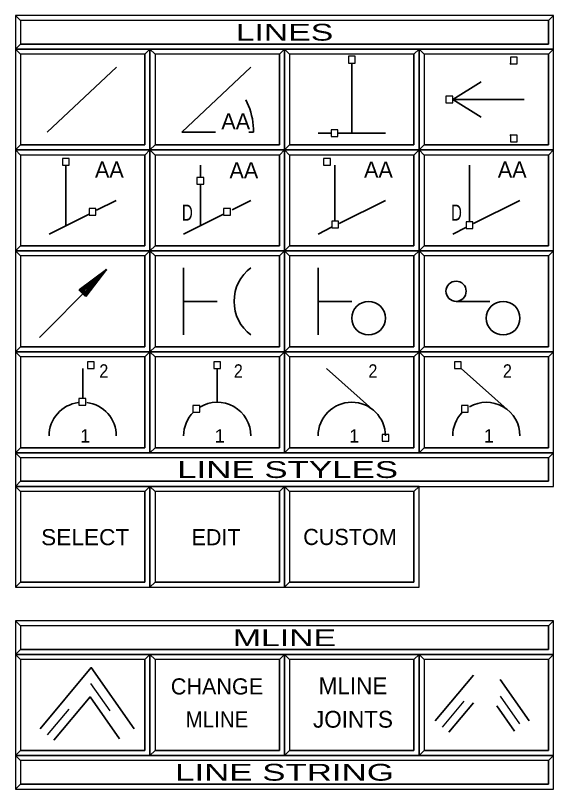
# Model space of a CAD drawing. Extents: x 95906.9 to 95918.9, y 90964.8 to 90972.9.
# Drawn here: x 95908.935 to 95910.535, y 90967.296 to 90969.589 of the extents above; entities that cross this region are included whole.
import ezdxf
from ezdxf.enums import TextEntityAlignment as Align

# ---------------------------------------------------------------- set-up
doc = ezdxf.new("R2010")
doc.units = 0
doc.header["$LTSCALE"] = 0.019
doc.linetypes.add('DOT_DASHED', pattern=[7.7, 5, -1.2, 0.3, -1.2])
doc.linetypes.add('MEDIUM_DASHED', pattern=[4.5, 3, -1.5])
for name, color, linetype, lineweight in [('1', 7, 'Continuous', 25), ('11', 7, 'Continuous', 25), ('12', 7, 'Continuous', 25), ('17', 7, 'Continuous', 25), ('2', 7, 'Continuous', 13), ('21', 7, 'Continuous', 25), ('3', 7, 'Continuous', 25), ('4', 7, 'Continuous', 35), ('6', 7, 'Continuous', 35), ('7', 7, 'Continuous', 35)]:
    doc.layers.add(name, color=color, linetype=linetype, lineweight=lineweight)

msp = doc.modelspace()

# ---------------------------------------------------------------- linework, layer by layer
at = {"layer": '1'}
for points in [[(95908.9346, 90969.4887), (95910.5346, 90969.4887), (95910.5346, 90969.5887), (95908.9346, 90969.5887)], [(95908.9346, 90969.1887), (95909.3346, 90969.1887), (95909.3346, 90969.4887), (95908.9346, 90969.4887)], [(95909.3346, 90969.1887), (95909.7346, 90969.1887), (95909.7346, 90969.4887), (95909.3346, 90969.4887)], [(95909.7346, 90969.1887), (95910.1346, 90969.1887), (95910.1346, 90969.4887), (95909.7346, 90969.4887)], [(95910.1346, 90969.1887), (95910.5346, 90969.1887), (95910.5346, 90969.4887), (95910.1346, 90969.4887)], [(95908.9346, 90968.8887), (95909.3346, 90968.8887), (95909.3346, 90969.1887), (95908.9346, 90969.1887)], [(95909.3346, 90968.8887), (95909.7346, 90968.8887), (95909.7346, 90969.1887), (95909.3346, 90969.1887)], [(95909.7346, 90968.8887), (95910.1346, 90968.8887), (95910.1346, 90969.1887), (95909.7346, 90969.1887)], [(95910.1346, 90968.8887), (95910.5346, 90968.8887), (95910.5346, 90969.1887), (95910.1346, 90969.1887)], [(95908.9346, 90968.5887), (95909.3346, 90968.5887), (95909.3346, 90968.8887), (95908.9346, 90968.8887)], [(95909.3346, 90968.5887), (95909.7346, 90968.5887), (95909.7346, 90968.8887), (95909.3346, 90968.8887)], [(95909.7346, 90968.5887), (95910.1346, 90968.5887), (95910.1346, 90968.8887), (95909.7346, 90968.8887)], [(95910.1346, 90968.5887), (95910.5346, 90968.5887), (95910.5346, 90968.8887), (95910.1346, 90968.8887)], [(95908.9346, 90968.2887), (95909.3346, 90968.2887), (95909.3346, 90968.5887), (95908.9346, 90968.5887)], [(95909.3346, 90968.2887), (95909.7346, 90968.2887), (95909.7346, 90968.5887), (95909.3346, 90968.5887)], [(95909.7346, 90968.2887), (95910.1346, 90968.2887), (95910.1346, 90968.5887), (95909.7346, 90968.5887)], [(95910.1346, 90968.2887), (95910.5346, 90968.2887), (95910.5346, 90968.5887), (95910.1346, 90968.5887)], [(95908.9346, 90968.1887), (95910.5346, 90968.1887), (95910.5346, 90968.2887), (95908.9346, 90968.2887)], [(95908.9346, 90967.8887), (95909.3346, 90967.8887), (95909.3346, 90968.1887), (95908.9346, 90968.1887)], [(95909.3346, 90967.8887), (95909.7346, 90967.8887), (95909.7346, 90968.1887), (95909.3346, 90968.1887)], [(95909.7346, 90967.8887), (95910.1346, 90967.8887), (95910.1346, 90968.1887), (95909.7346, 90968.1887)], [(95908.9346, 90967.6887), (95910.5346, 90967.6887), (95910.5346, 90967.7887), (95908.9346, 90967.7887)], [(95908.9346, 90967.3887), (95909.3346, 90967.3887), (95909.3346, 90967.6887), (95908.9346, 90967.6887)], [(95909.3346, 90967.3887), (95909.7346, 90967.3887), (95909.7346, 90967.6887), (95909.3346, 90967.6887)], [(95909.7346, 90967.3887), (95910.1346, 90967.3887), (95910.1346, 90967.6887), (95909.7346, 90967.6887)], [(95910.1346, 90967.3887), (95910.5346, 90967.3887), (95910.5346, 90967.6887), (95910.1346, 90967.6887)], [(95908.9346, 90967.2887), (95910.5346, 90967.2887), (95910.5346, 90967.3887), (95908.9346, 90967.3887)]]:
    msp.add_lwpolyline(points, close=True, dxfattribs=at)
at = {"layer": '11'}
for points in [[(95908.9496, 90969.2037), (95909.3196, 90969.2037), (95909.3196, 90969.4737), (95908.9496, 90969.4737)], [(95909.3496, 90969.2037), (95909.7196, 90969.2037), (95909.7196, 90969.4737), (95909.3496, 90969.4737)], [(95909.7496, 90969.2037), (95910.1196, 90969.2037), (95910.1196, 90969.4737), (95909.7496, 90969.4737)], [(95910.1496, 90969.2037), (95910.5196, 90969.2037), (95910.5196, 90969.4737), (95910.1496, 90969.4737)], [(95908.9496, 90968.9037), (95909.3196, 90968.9037), (95909.3196, 90969.1737), (95908.9496, 90969.1737)], [(95909.3496, 90968.9037), (95909.7196, 90968.9037), (95909.7196, 90969.1737), (95909.3496, 90969.1737)], [(95909.7496, 90968.9037), (95910.1196, 90968.9037), (95910.1196, 90969.1737), (95909.7496, 90969.1737)], [(95910.1496, 90968.9037), (95910.5196, 90968.9037), (95910.5196, 90969.1737), (95910.1496, 90969.1737)], [(95908.9496, 90968.6037), (95909.3196, 90968.6037), (95909.3196, 90968.8737), (95908.9496, 90968.8737)], [(95909.3496, 90968.6037), (95909.7196, 90968.6037), (95909.7196, 90968.8737), (95909.3496, 90968.8737)], [(95909.7496, 90968.6037), (95910.1196, 90968.6037), (95910.1196, 90968.8737), (95909.7496, 90968.8737)], [(95910.1496, 90968.6037), (95910.5196, 90968.6037), (95910.5196, 90968.8737), (95910.1496, 90968.8737)], [(95908.9496, 90968.3037), (95909.3196, 90968.3037), (95909.3196, 90968.5737), (95908.9496, 90968.5737)], [(95909.3496, 90968.3037), (95909.7196, 90968.3037), (95909.7196, 90968.5737), (95909.3496, 90968.5737)], [(95909.7496, 90968.3037), (95910.1196, 90968.3037), (95910.1196, 90968.5737), (95909.7496, 90968.5737)], [(95910.1496, 90968.3037), (95910.5196, 90968.3037), (95910.5196, 90968.5737), (95910.1496, 90968.5737)], [(95908.9496, 90967.9037), (95909.3196, 90967.9037), (95909.3196, 90968.1737), (95908.9496, 90968.1737)], [(95909.3496, 90967.9037), (95909.7196, 90967.9037), (95909.7196, 90968.1737), (95909.3496, 90968.1737)], [(95909.7496, 90967.9037), (95910.1196, 90967.9037), (95910.1196, 90968.1737), (95909.7496, 90968.1737)], [(95908.9496, 90967.4037), (95909.3196, 90967.4037), (95909.3196, 90967.6737), (95908.9496, 90967.6737)], [(95909.3496, 90967.4037), (95909.7196, 90967.4037), (95909.7196, 90967.6737), (95909.3496, 90967.6737)], [(95909.7496, 90967.4037), (95910.1196, 90967.4037), (95910.1196, 90967.6737), (95909.7496, 90967.6737)], [(95910.1496, 90967.4037), (95910.5196, 90967.4037), (95910.5196, 90967.6737), (95910.1496, 90967.6737)]]:
    msp.add_lwpolyline(points, close=True, dxfattribs=at)
at = {"layer": '12'}
msp.add_lwpolyline([(95908.9496, 90969.2037), (95909.3196, 90969.2037), (95909.3196, 90969.4737), (95908.9496, 90969.4737)], close=True, dxfattribs=at)
at = {"layer": '17'}
for points in [[(95908.9496, 90969.5037), (95910.5196, 90969.5037), (95910.5196, 90969.5737), (95908.9496, 90969.5737)], [(95908.9496, 90967.7037), (95910.5196, 90967.7037), (95910.5196, 90967.7737), (95908.9496, 90967.7737)], [(95908.9496, 90967.3037), (95910.5196, 90967.3037), (95910.5196, 90967.3737), (95908.9496, 90967.3737)]]:
    msp.add_lwpolyline(points, close=True, dxfattribs=at)
at = {"layer": '2'}
for points in [[(95908.9346, 90969.5887), (95908.9346, 90969.4887), (95908.9496, 90969.5037), (95908.9496, 90969.5737), (95910.5196, 90969.5737), (95910.5346, 90969.5887)], [(95908.9346, 90969.4887), (95908.9346, 90969.1887), (95908.9496, 90969.2037), (95908.9496, 90969.4737), (95909.3196, 90969.4737), (95909.3346, 90969.4887)], [(95909.3346, 90969.4887), (95909.3346, 90969.1887), (95909.3496, 90969.2037), (95909.3496, 90969.4737), (95909.7196, 90969.4737), (95909.7346, 90969.4887)], [(95909.7346, 90969.4887), (95909.7346, 90969.1887), (95909.7496, 90969.2037), (95909.7496, 90969.4737), (95910.1196, 90969.4737), (95910.1346, 90969.4887)], [(95910.1346, 90969.4887), (95910.1346, 90969.1887), (95910.1496, 90969.2037), (95910.1496, 90969.4737), (95910.5196, 90969.4737), (95910.5346, 90969.4887)], [(95908.9346, 90969.1887), (95908.9346, 90968.8887), (95908.9496, 90968.9037), (95908.9496, 90969.1737), (95909.3196, 90969.1737), (95909.3346, 90969.1887)], [(95909.3346, 90969.1887), (95909.3346, 90968.8887), (95909.3496, 90968.9037), (95909.3496, 90969.1737), (95909.7196, 90969.1737), (95909.7346, 90969.1887)], [(95909.7346, 90969.1887), (95909.7346, 90968.8887), (95909.7496, 90968.9037), (95909.7496, 90969.1737), (95910.1196, 90969.1737), (95910.1346, 90969.1887)], [(95910.1346, 90969.1887), (95910.1346, 90968.8887), (95910.1496, 90968.9037), (95910.1496, 90969.1737), (95910.5196, 90969.1737), (95910.5346, 90969.1887)], [(95908.9346, 90968.8887), (95908.9346, 90968.5887), (95908.9496, 90968.6037), (95908.9496, 90968.8737), (95909.3196, 90968.8737), (95909.3346, 90968.8887)], [(95909.3346, 90968.8887), (95909.3346, 90968.5887), (95909.3496, 90968.6037), (95909.3496, 90968.8737), (95909.7196, 90968.8737), (95909.7346, 90968.8887)], [(95909.7346, 90968.8887), (95909.7346, 90968.5887), (95909.7496, 90968.6037), (95909.7496, 90968.8737), (95910.1196, 90968.8737), (95910.1346, 90968.8887)], [(95910.1346, 90968.8887), (95910.1346, 90968.5887), (95910.1496, 90968.6037), (95910.1496, 90968.8737), (95910.5196, 90968.8737), (95910.5346, 90968.8887)], [(95908.9346, 90968.5887), (95908.9346, 90968.2887), (95908.9496, 90968.3037), (95908.9496, 90968.5737), (95909.3196, 90968.5737), (95909.3346, 90968.5887)], [(95909.3346, 90968.5887), (95909.3346, 90968.2887), (95909.3496, 90968.3037), (95909.3496, 90968.5737), (95909.7196, 90968.5737), (95909.7346, 90968.5887)], [(95909.7346, 90968.5887), (95909.7346, 90968.2887), (95909.7496, 90968.3037), (95909.7496, 90968.5737), (95910.1196, 90968.5737), (95910.1346, 90968.5887)], [(95910.1346, 90968.5887), (95910.1346, 90968.2887), (95910.1496, 90968.3037), (95910.1496, 90968.5737), (95910.5196, 90968.5737), (95910.5346, 90968.5887)], [(95908.9346, 90968.2887), (95908.9346, 90968.1887), (95908.9496, 90968.2037), (95908.9496, 90968.2737), (95910.5196, 90968.2737), (95910.5346, 90968.2887)], [(95908.9346, 90968.1887), (95908.9346, 90967.8887), (95908.9496, 90967.9037), (95908.9496, 90968.1737), (95909.3196, 90968.1737), (95909.3346, 90968.1887)], [(95909.3346, 90968.1887), (95909.3346, 90967.8887), (95909.3496, 90967.9037), (95909.3496, 90968.1737), (95909.7196, 90968.1737), (95909.7346, 90968.1887)], [(95909.7346, 90968.1887), (95909.7346, 90967.8887), (95909.7496, 90967.9037), (95909.7496, 90968.1737), (95910.1196, 90968.1737), (95910.1346, 90968.1887)], [(95909.7346, 90968.1887), (95909.7346, 90967.8887), (95909.7496, 90967.9037), (95909.7496, 90968.1737), (95910.1196, 90968.1737), (95910.1346, 90968.1887)], [(95908.9346, 90967.7887), (95908.9346, 90967.6887), (95908.9496, 90967.7037), (95908.9496, 90967.7737), (95910.5196, 90967.7737), (95910.5346, 90967.7887)], [(95908.9346, 90967.6887), (95908.9346, 90967.3887), (95908.9496, 90967.4037), (95908.9496, 90967.6737), (95909.3196, 90967.6737), (95909.3346, 90967.6887)], [(95909.3346, 90967.6887), (95909.3346, 90967.3887), (95909.3496, 90967.4037), (95909.3496, 90967.6737), (95909.7196, 90967.6737), (95909.7346, 90967.6887)], [(95909.7346, 90967.6887), (95909.7346, 90967.3887), (95909.7496, 90967.4037), (95909.7496, 90967.6737), (95910.1196, 90967.6737), (95910.1346, 90967.6887)], [(95910.1346, 90967.6887), (95910.1346, 90967.3887), (95910.1496, 90967.4037), (95910.1496, 90967.6737), (95910.5196, 90967.6737), (95910.5346, 90967.6887)], [(95908.9346, 90967.3887), (95908.9346, 90967.2887), (95908.9496, 90967.3037), (95908.9496, 90967.3737), (95910.5196, 90967.3737), (95910.5346, 90967.3887)]]:
    msp.add_lwpolyline(points, close=True, dxfattribs=at)
at = {"layer": '21'}
msp.add_lwpolyline([(95908.9496, 90968.2037), (95910.5196, 90968.2037), (95910.5196, 90968.2737), (95908.9496, 90968.2737)], close=True, dxfattribs=at)
at = {"layer": '3'}
for points in [[(95908.9346, 90969.4887), (95910.5346, 90969.4887), (95910.5346, 90969.5887), (95910.5196, 90969.5737), (95910.5196, 90969.5037), (95908.9496, 90969.5037)], [(95908.9346, 90969.1887), (95909.3346, 90969.1887), (95909.3346, 90969.4887), (95909.3196, 90969.4737), (95909.3196, 90969.2037), (95908.9496, 90969.2037)], [(95909.3346, 90969.1887), (95909.7346, 90969.1887), (95909.7346, 90969.4887), (95909.7196, 90969.4737), (95909.7196, 90969.2037), (95909.3496, 90969.2037)], [(95909.7346, 90969.1887), (95910.1346, 90969.1887), (95910.1346, 90969.4887), (95910.1196, 90969.4737), (95910.1196, 90969.2037), (95909.7496, 90969.2037)], [(95910.1346, 90969.1887), (95910.5346, 90969.1887), (95910.5346, 90969.4887), (95910.5196, 90969.4737), (95910.5196, 90969.2037), (95910.1496, 90969.2037)], [(95908.9346, 90968.8887), (95909.3346, 90968.8887), (95909.3346, 90969.1887), (95909.3196, 90969.1737), (95909.3196, 90968.9037), (95908.9496, 90968.9037)], [(95909.3346, 90968.8887), (95909.7346, 90968.8887), (95909.7346, 90969.1887), (95909.7196, 90969.1737), (95909.7196, 90968.9037), (95909.3496, 90968.9037)], [(95909.7346, 90968.8887), (95910.1346, 90968.8887), (95910.1346, 90969.1887), (95910.1196, 90969.1737), (95910.1196, 90968.9037), (95909.7496, 90968.9037)], [(95910.1346, 90968.8887), (95910.5346, 90968.8887), (95910.5346, 90969.1887), (95910.5196, 90969.1737), (95910.5196, 90968.9037), (95910.1496, 90968.9037)], [(95908.9346, 90968.5887), (95909.3346, 90968.5887), (95909.3346, 90968.8887), (95909.3196, 90968.8737), (95909.3196, 90968.6037), (95908.9496, 90968.6037)], [(95909.3346, 90968.5887), (95909.7346, 90968.5887), (95909.7346, 90968.8887), (95909.7196, 90968.8737), (95909.7196, 90968.6037), (95909.3496, 90968.6037)], [(95909.7346, 90968.5887), (95910.1346, 90968.5887), (95910.1346, 90968.8887), (95910.1196, 90968.8737), (95910.1196, 90968.6037), (95909.7496, 90968.6037)], [(95910.1346, 90968.5887), (95910.5346, 90968.5887), (95910.5346, 90968.8887), (95910.5196, 90968.8737), (95910.5196, 90968.6037), (95910.1496, 90968.6037)], [(95908.9346, 90968.2887), (95909.3346, 90968.2887), (95909.3346, 90968.5887), (95909.3196, 90968.5737), (95909.3196, 90968.3037), (95908.9496, 90968.3037)], [(95909.3346, 90968.2887), (95909.7346, 90968.2887), (95909.7346, 90968.5887), (95909.7196, 90968.5737), (95909.7196, 90968.3037), (95909.3496, 90968.3037)], [(95909.7346, 90968.2887), (95910.1346, 90968.2887), (95910.1346, 90968.5887), (95910.1196, 90968.5737), (95910.1196, 90968.3037), (95909.7496, 90968.3037)], [(95910.1346, 90968.2887), (95910.5346, 90968.2887), (95910.5346, 90968.5887), (95910.5196, 90968.5737), (95910.5196, 90968.3037), (95910.1496, 90968.3037)], [(95908.9346, 90968.1887), (95910.5346, 90968.1887), (95910.5346, 90968.2887), (95910.5196, 90968.2737), (95910.5196, 90968.2037), (95908.9496, 90968.2037)], [(95908.9346, 90967.8887), (95909.3346, 90967.8887), (95909.3346, 90968.1887), (95909.3196, 90968.1737), (95909.3196, 90967.9037), (95908.9496, 90967.9037)], [(95909.3346, 90967.8887), (95909.7346, 90967.8887), (95909.7346, 90968.1887), (95909.7196, 90968.1737), (95909.7196, 90967.9037), (95909.3496, 90967.9037)], [(95909.7346, 90967.8887), (95910.1346, 90967.8887), (95910.1346, 90968.1887), (95910.1196, 90968.1737), (95910.1196, 90967.9037), (95909.7496, 90967.9037)], [(95908.9346, 90967.6887), (95910.5346, 90967.6887), (95910.5346, 90967.7887), (95910.5196, 90967.7737), (95910.5196, 90967.7037), (95908.9496, 90967.7037)], [(95908.9346, 90967.3887), (95909.3346, 90967.3887), (95909.3346, 90967.6887), (95909.3196, 90967.6737), (95909.3196, 90967.4037), (95908.9496, 90967.4037)], [(95909.3346, 90967.3887), (95909.7346, 90967.3887), (95909.7346, 90967.6887), (95909.7196, 90967.6737), (95909.7196, 90967.4037), (95909.3496, 90967.4037)], [(95909.7346, 90967.3887), (95910.1346, 90967.3887), (95910.1346, 90967.6887), (95910.1196, 90967.6737), (95910.1196, 90967.4037), (95909.7496, 90967.4037)], [(95910.1346, 90967.3887), (95910.5346, 90967.3887), (95910.5346, 90967.6887), (95910.5196, 90967.6737), (95910.5196, 90967.4037), (95910.1496, 90967.4037)], [(95908.9346, 90967.2887), (95910.5346, 90967.2887), (95910.5346, 90967.3887), (95910.5196, 90967.3737), (95910.5196, 90967.3037), (95908.9496, 90967.3037)]]:
    msp.add_lwpolyline(points, close=True, dxfattribs=at)
at = {"layer": '4'}
for p, q in [((95908.9496, 90969.5737), (95908.9346, 90969.5887)), ((95908.9496, 90969.4737), (95908.9346, 90969.4887)), ((95909.3496, 90969.4737), (95909.3346, 90969.4887)), ((95909.7496, 90969.4737), (95909.7346, 90969.4887)), ((95910.1496, 90969.4737), (95910.1346, 90969.4887)), ((95908.9496, 90969.1737), (95908.9346, 90969.1887)), ((95909.3496, 90969.1737), (95909.3346, 90969.1887)), ((95909.7496, 90969.1737), (95909.7346, 90969.1887)), ((95910.1496, 90969.1737), (95910.1346, 90969.1887)), ((95908.9496, 90968.8737), (95908.9346, 90968.8887)), ((95909.3496, 90968.8737), (95909.3346, 90968.8887)), ((95909.7496, 90968.8737), (95909.7346, 90968.8887)), ((95910.1496, 90968.8737), (95910.1346, 90968.8887)), ((95908.9496, 90968.5737), (95908.9346, 90968.5887)), ((95909.3496, 90968.5737), (95909.3346, 90968.5887)), ((95909.7496, 90968.5737), (95909.7346, 90968.5887)), ((95910.1496, 90968.5737), (95910.1346, 90968.5887)), ((95908.9496, 90968.2737), (95908.9346, 90968.2887)), ((95908.9496, 90968.1737), (95908.9346, 90968.1887)), ((95909.3496, 90968.1737), (95909.3346, 90968.1887)), ((95909.7496, 90968.1737), (95909.7346, 90968.1887)), ((95908.9496, 90967.7737), (95908.9346, 90967.7887)), ((95908.9496, 90967.6737), (95908.9346, 90967.6887)), ((95909.3496, 90967.6737), (95909.3346, 90967.6887)), ((95909.7496, 90967.6737), (95909.7346, 90967.6887)), ((95910.1496, 90967.6737), (95910.1346, 90967.6887)), ((95908.9496, 90967.3737), (95908.9346, 90967.3887))]:
    msp.add_line(p, q, dxfattribs=at)
at = {"layer": '6'}
for p, q in [((95909.029, 90969.2412), (95909.235, 90969.435)), ((95909.429, 90969.2412), (95909.635, 90969.435)), ((95909.9346, 90969.2387), (95909.9346, 90969.4472)), ((95910.2346, 90969.3387), (95910.4467, 90969.3387)), ((95909.8346, 90969.2387), (95909.871, 90969.2387)), ((95910.0346, 90969.2387), (95909.8929, 90969.2387)), ((95909.0846, 90968.9637), (95909.0846, 90969.1437)), ((95909.4846, 90969.1437), (95909.4846, 90969.1098)), ((95909.8846, 90969.1437), (95909.8846, 90968.9781)), ((95910.2846, 90969.1437), (95910.2846, 90968.9755)), ((95909.4846, 90968.9637), (95909.4846, 90969.0853)), ((95909.2346, 90969.0387), (95909.176, 90969.0094)), ((95909.6346, 90969.0387), (95909.5795, 90969.0112)), ((95910.0346, 90969.0387), (95909.8969, 90968.9699)), ((95910.4346, 90969.0387), (95910.2969, 90968.9698)), ((95909.0346, 90968.9387), (95909.1534, 90968.9981)), ((95909.4346, 90968.9387), (95909.5532, 90968.998)), ((95909.8346, 90968.9387), (95909.8747, 90968.9588)), ((95910.2346, 90968.9387), (95910.2736, 90968.9582)), ((95909.4346, 90968.8387), (95909.4346, 90968.6387)), ((95909.8346, 90968.8387), (95909.8346, 90968.6387)), ((95909.1639, 90968.7895), (95909.0059, 90968.6315)), ((95909.1346, 90968.5387), (95909.1346, 90968.4525)), ((95909.5346, 90968.4387), (95909.5346, 90968.5387)), ((95910.0053, 90968.4094), (95909.8596, 90968.5387)), ((95910.4053, 90968.4094), (95910.2596, 90968.5387)), ((95910.1827, 90967.4916), (95910.2965, 90967.6273)), ((95910.376, 90967.6147), (95910.4622, 90967.4916)), ((95910.2233, 90967.4576), (95910.2965, 90967.5449)), ((95910.3661, 90967.5365), (95910.4188, 90967.4612))]:
    msp.add_line(p, q, dxfattribs=at)
at = {"layer": '6', "linetype": 'MEDIUM_DASHED'}
for p, q in [((95910.2346, 90969.3387), (95910.4063, 90969.4443)), ((95910.2346, 90969.3387), (95910.4063, 90969.2331)), ((95909.429, 90969.2412), (95909.6429, 90969.2412)), ((95909.4346, 90968.7387), (95909.5846, 90968.7387)), ((95909.8346, 90968.7387), (95909.9846, 90968.7387)), ((95910.2446, 90968.7387), (95910.3846, 90968.7387))]:
    msp.add_line(p, q, dxfattribs=at)
at = {"layer": '6', "lineweight": 40}
for p, q in [((95909.205, 90968.8333), (95909.1242, 90968.7727)), ((95909.205, 90968.8333), (95909.1441, 90968.7528)), ((95909.1905, 90968.8188), (95909.1285, 90968.7724)), ((95909.1905, 90968.8188), (95909.1438, 90968.7573)), ((95909.1758, 90968.8042), (95909.133, 90968.7721)), ((95909.1612, 90968.7897), (95909.1374, 90968.7718)), ((95909.1612, 90968.7897), (95909.1432, 90968.766)), ((95909.1758, 90968.8042), (95909.1435, 90968.7616)), ((95909.1441, 90968.7528), (95909.1242, 90968.7727)), ((95909.1438, 90968.7573), (95909.1285, 90968.7724)), ((95909.1435, 90968.7616), (95909.133, 90968.7721)), ((95909.1432, 90968.766), (95909.1374, 90968.7718))]:
    msp.add_line(p, q, dxfattribs=at)
at = {"layer": '6', "linetype": 'DOT_DASHED', "lineweight": 25}
for p, q in [((95910.2045, 90967.4733), (95910.2965, 90967.583)), ((95910.376, 90967.5651), (95910.4389, 90967.4753))]:
    msp.add_line(p, q, dxfattribs=at)
at = {"layer": '6', "lineweight": 25}
for points in [[(95909.9246, 90969.4472), (95909.9446, 90969.4472), (95909.9446, 90969.4672), (95909.9246, 90969.4672)], [(95910.4063, 90969.4443), (95910.4263, 90969.4443), (95910.4263, 90969.4643), (95910.4063, 90969.4643)], [(95910.2146, 90969.3287), (95910.2346, 90969.3287), (95910.2346, 90969.3487), (95910.2146, 90969.3487)], [(95909.8729, 90969.2289), (95909.8929, 90969.2289), (95909.8929, 90969.2489), (95909.8729, 90969.2489)], [(95910.4063, 90969.2131), (95910.4263, 90969.2131), (95910.4263, 90969.2331), (95910.4063, 90969.2331)], [(95909.0746, 90969.1437), (95909.0946, 90969.1437), (95909.0946, 90969.1637), (95909.0746, 90969.1637)], [(95909.8509, 90969.1437), (95909.8709, 90969.1437), (95909.8709, 90969.1637), (95909.8509, 90969.1637)], [(95909.4743, 90969.0872), (95909.4943, 90969.0872), (95909.4943, 90969.1072), (95909.4743, 90969.1072)], [(95909.1536, 90968.995), (95909.1736, 90968.995), (95909.1736, 90969.015), (95909.1536, 90969.015)], [(95909.5536, 90968.995), (95909.5736, 90968.995), (95909.5736, 90969.015), (95909.5536, 90969.015)], [(95909.8754, 90968.9574), (95909.8954, 90968.9574), (95909.8954, 90968.9774), (95909.8754, 90968.9774)], [(95910.275, 90968.9555), (95910.295, 90968.9555), (95910.295, 90968.9755), (95910.275, 90968.9755)], [(95909.1486, 90968.5387), (95909.1686, 90968.5387), (95909.1686, 90968.5587), (95909.1486, 90968.5587)], [(95909.5246, 90968.5387), (95909.5446, 90968.5387), (95909.5446, 90968.5587), (95909.5246, 90968.5587)], [(95910.2396, 90968.5387), (95910.2596, 90968.5387), (95910.2596, 90968.5587), (95910.2396, 90968.5587)], [(95909.1236, 90968.4299), (95909.1436, 90968.4299), (95909.1436, 90968.4499), (95909.1236, 90968.4499)], [(95909.4625, 90968.4092), (95909.4825, 90968.4092), (95909.4825, 90968.4292), (95909.4625, 90968.4292)], [(95910.2604, 90968.4092), (95910.2804, 90968.4092), (95910.2804, 90968.4292), (95910.2604, 90968.4292)], [(95910.0249, 90968.3226), (95910.0449, 90968.3226), (95910.0449, 90968.3426), (95910.0249, 90968.3426)]]:
    msp.add_lwpolyline(points, close=True, dxfattribs=at)
at = {"layer": '6'}
for points in [[(95909.0079, 90967.4681), (95909.1602, 90967.6497), (95909.2874, 90967.4681)], [(95909.0485, 90967.4341), (95909.1564, 90967.5628), (95909.244, 90967.4377)]]:
    msp.add_lwpolyline(points, dxfattribs=at)
at = {"layer": '6', "linetype": 'DOT_DASHED', "lineweight": 25}
msp.add_lwpolyline([(95909.0297, 90967.4498), (95909.1582, 90967.603), (95909.2641, 90967.4518)], dxfattribs=at)
at = {"layer": '6'}
for centre, radius in [((95910.2446, 90968.7687), 0.03), ((95909.9846, 90968.6887), 0.05), ((95910.3846, 90968.6887), 0.05)]:
    msp.add_circle(centre, radius, dxfattribs=at)
at = {"layer": '6', "linetype": 'MEDIUM_DASHED'}
msp.add_arc((95909.429, 90969.2412), 0.2139, 0, 43.2522, dxfattribs=at)
at = {"layer": '6'}
for centre, radius, start, end in [((95909.7096, 90968.7387), 0.125, 126.8699, 233.1301), ((95909.1346, 90968.3387), 0.1, 97.558, 180), ((95909.1346, 90968.3387), 0.1, 0, 82.9369), ((95909.5346, 90968.3387), 0.1, 0, 121.3266), ((95909.9346, 90968.3387), 0.1, 0, 180), ((95910.3346, 90968.3387), 0.1, 0, 119.9911), ((95909.5346, 90968.3387), 0.1, 135.1578, 180), ((95910.3346, 90968.3387), 0.1, 136.7381, 180)]:
    msp.add_arc(centre, radius, start, end, dxfattribs=at)

# ---------------------------------------------------------------- texts
for s, height, p in [('AA', 0.048, (95909.5896, 90969.2499)), ('AA', 0.048, (95909.2139, 90969.1065)), ('AA', 0.048, (95909.6138, 90969.1043)), ('AA', 0.048, (95910.0139, 90969.1064)), ('AA', 0.048, (95910.4116, 90969.1065)), ('1', 0.04, (95909.1421, 90968.3187)), ('1', 0.04, (95909.5421, 90968.3187)), ('1', 0.04, (95909.9421, 90968.3187)), ('1', 0.04, (95910.3421, 90968.3187)), ('EDIT', 0.048, (95909.5311, 90968.0136)), ('CUSTOM', 0.048, (95909.9293, 90968.0143)), ('CHANGE', 0.048, (95909.5339, 90967.57)), ('MLINE', 0.04999, (95909.9382, 90967.5707)), ('JOINTS', 0.04999, (95909.9382, 90967.4713))]:
    msp.add_text(s, height=height, dxfattribs=at).set_placement(p, align=Align.CENTER)
for s, height, width, p in [('D', 0.048, 0.7, (95909.4458, 90968.9785)), ('D', 0.048, 0.7, (95910.2458, 90968.9785)), ('2', 0.04, 0.9, (95909.1974, 90968.5116)), ('2', 0.04, 0.9, (95909.5973, 90968.5116)), ('2', 0.04, 0.9, (95909.9974, 90968.5116)), ('2', 0.04, 0.9, (95910.3973, 90968.5116)), ('SELECT', 0.048, 1.05, (95909.142, 90968.0137)), ('MLINE', 0.048, 0.95, (95909.5339, 90967.472))]:
    msp.add_text(s, height=height, dxfattribs=dict(at, width=width)).set_placement(p, align=Align.CENTER)
at = {"layer": '7'}
for s, height, width, p in [('         LINES         ', 0.04999, 1.5, (95909.7346, 90969.5137)), ('    LINE STYLES    ', 0.05, 1.55, (95909.7438, 90968.2136)), ('         MLINE         ', 0.04999, 1.5, (95909.7345, 90967.7137)), ('      LINE STRING      ', 0.04999, 1.55, (95909.7345, 90967.3137))]:
    msp.add_text(s, height=height, dxfattribs=dict(at, width=width)).set_placement(p, align=Align.CENTER)

doc.saveas('drawing.dxf')
